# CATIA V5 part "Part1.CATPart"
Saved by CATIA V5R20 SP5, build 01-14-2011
Part number: 饮料瓶
Bounding box of the stored display mesh (mm): x -25 to 26, y -25 to 180.655, z 0 to 110
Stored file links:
  E:\饮料瓶\Part1.CATPart
  C:\Program Files\Dassault Systemes\B20\intel_a\startup\materials\Catalog.CATMaterial
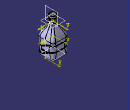
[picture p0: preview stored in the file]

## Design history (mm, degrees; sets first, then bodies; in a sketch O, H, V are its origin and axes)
Set1
  Sketch1 on xy-plane, origin (0, 0, 0), H (1, 0, 0), V (0, 1, 0)
    line L1 (25, 25) -> (25, -25)
    line L2 (25, -25) -> (-25, -25)
    line L3 (-25, -25) -> (-25, 25)
    line L4 (-25, 25) -> (25, 25)
    length L1 = 50
    length L2 = 50
    vertical: L1 V, L3 V
    horizontal: L2 H, L4 H
    equidistance: L1 L3 O, L2 L4 O
  Sketch2 on face of Pad1 from Sketch1.L3, origin (-25, 0, 0), H (0, -1, 0), V (0, 0, 1)
    spline S1 through (-40, 10) (-10, 20) (20, 10) (30, 20) (40, 30)
  Extrude1: Element1 Sketch2, Lim1 80, Lim2 80
  MultiSel1: CommonCtxFeats ({extract ExtractElem face of Pad1 from Sketch1.L3}; {extract ExtractElem face of Fillet1}; {extract ExtractElem face of Pad1 from Sketch1.L2}; {extract ExtractElem face of Fillet1}; {extract ExtractElem face of Pad1 from Sketch1.L1}; {extract ExtractElem face of Fillet1}; {extract ExtractElem face of Pad1 from Sketch1.L4}; {extract ExtractElem face of Fillet1})
  Sketch3 on face of Pad1 from Sketch1.L2, origin (0, -25, 0), H (1, 0, 0), V (0, 0, 1)
    spline S1 through (-30, 30) (-10, 40) (20, 30) (40, 40)
  Extrude2: Element1 Sketch3, Lim1 80, Lim2 80
  Sketch4 on face of Pad1 from Sketch1.L3, origin (-25, 0, 0), H (0, -1, 0), V (0, 0, 1)
    spline S1 through (-40, 30) (-10, 40) (10, 30) (50, 40)
  Extrude3: Element1 Sketch4, Lim1 80, Lim2 80
  MultiSel2: CommonCtxFeats ({extract ExtractElem face of Pad1 from Sketch1.L3}; {extract ExtractElem face of Fillet1}; {extract ExtractElem face of Pad1 from Sketch1.L2}; {extract ExtractElem face of Fillet1}; {extract ExtractElem face of Pad1 from Sketch1.L1}; {extract ExtractElem face of Fillet1}; {extract ExtractElem face of Pad1 from Sketch1.L4}; {extract ExtractElem face of Fillet1})
  Join1: Elements ({intersect ToIntersect1 {extract ExtractElem face of Pad1 from Sketch1.L3}, ToIntersect2 Extrude1}; {intersect ToIntersect1 {extract ExtractElem face of Fillet1}, ToIntersect2 Extrude1}; {intersect ToIntersect1 {extract ExtractElem face of Pad1 from Sketch1.L2}, ToIntersect2 Extrude1}; {intersect ToIntersect1 {extract ExtractElem face of Fillet1}, ToIntersect2 Extrude1}; {intersect ToIntersect1 {extract ExtractElem face of Pad1 from Sketch1.L1}, ToIntersect2 Extrude1}; {intersect ToIntersect1 {extract ExtractElem face of Fillet1}, ToIntersect2 Extrude1}; {intersect ToIntersect1 {extract ExtractElem face of Pad1 from Sketch1.L4}, ToIntersect2 Extrude1}; {intersect ToIntersect1 {extract ExtractElem face of Fillet1}, ToIntersect2 Extrude1})
  Join2: Elements ({intersect ToIntersect1 {extract ExtractElem face of Pad1 from Sketch1.L3}, ToIntersect2 Extrude3}; {intersect ToIntersect1 {extract ExtractElem face of Fillet1}, ToIntersect2 Extrude3}; {intersect ToIntersect1 {extract ExtractElem face of Pad1 from Sketch1.L2}, ToIntersect2 Extrude3}; {intersect ToIntersect1 {extract ExtractElem face of Fillet1}, ToIntersect2 Extrude3}; {intersect ToIntersect1 {extract ExtractElem face of Pad1 from Sketch1.L1}, ToIntersect2 Extrude3}; {intersect ToIntersect1 {extract ExtractElem face of Fillet1}, ToIntersect2 Extrude3}; {intersect ToIntersect1 {extract ExtractElem face of Pad1 from Sketch1.L4}, ToIntersect2 Extrude3}; {intersect ToIntersect1 {extract ExtractElem face of Fillet1}, ToIntersect2 Extrude3})
  Plane1: type Normal, Curve Join1, RefPoint vertex [face of MultiSel1 | face of MultiSel1]
  Circle1: type CtrRad, Start 0, End 180, Center vertex [face of MultiSel1 | face of MultiSel1], Support Plane1, Radius 1, FirstDirection (1, 0, 0)
  Plane2: type Normal, Curve Join2, RefPoint vertex [face of MultiSel2 | face of MultiSel2]
  Circle2: type CtrRad, Start 0, End 180, Center vertex [face of MultiSel2 | face of MultiSel2], Support Plane2, Radius 1, FirstDirection (0, 1, 0)
Body1 (main body)
  Pad1: profile Sketch1, direction (0, 0, 1), length 50
  Fillet1: on edge [face of Pad1 from Sketch1.L2 | face of Pad1 from Sketch1.L3]; edge [face of Pad1 from Sketch1.L3 | face of Pad1 from Sketch1.L4]; edge [face of Pad1 from Sketch1.L4 | face of Pad1 from Sketch1.L1]; edge [face of Pad1 from Sketch1.L1 | face of Pad1 from Sketch1.L2]
  Plane3: type Offset, RefPlane xy-plane, Offset 90
  Sketch5 on Plane3, origin (0, 0, 90), H (1, 0, 0), V (0, 1, 0)
    circle A1 centre (0, 0) radius 10
  Pad2: profile Sketch5, direction (0, 0, 1), length 20
  Fillet2: radius 5, on edge [start face of Pad1 | face of Pad1 from Sketch1.L2]
  Sketch6 on end face of Pad1, origin (0, 0, 50), H (1, 0, 0), V (0, 1, 0)
    point P1 (25, 0)
    distance V P1 = 25
  Sketch7 on Plane3, origin (0, 0, 90), H (1, 0, 0), V (0, 1, 0)
    point P1 (10, 0)
    distance V P1 = 10
    coincidence: P1 H
  Loft1: solid, Sections ({boundary Boundary {extract ExtractElem start face of Pad2}}; {boundary Boundary {extract ExtractElem end face of Pad1}}), StartFace start face of Pad2, EndFace end face of Pad1
  Slot1: profile Circle2, centre curve Join2
  Slot2: profile Circle1, centre curve Join1
  Shell1: ExtOffset 0, Face end face of Pad2, IntOffset 1
  Plane4: type Offset, RefPlane xy-plane, Offset 92
  Sketch8 on Plane4, origin (0, 0, 92), H (1, 0, 0), V (0, 1, 0)
    point P1 (10, 0)
    distance O P1 = 10
    coincidence: P1 H
  Helix1: Direction Z axis, RefPoint Sketch8, Pitch 3, Height 15, TaperAngle 0
  Point1: type OnCurve, Support Helix1, Length 5
  Point2: type OnCurve, Support Helix1, Length 5
  Line1: type PtDir, RefPoint vertex of Helix1, Direction (1, 0, 0), Start 0, End -5
  Line2: type PtDir, RefPoint Sketch8, Direction (1, 0, 0), Start 0, End -5
  Connect1: Curve1 Line2, Point1 vertex of Line2, Tension1 1, Curve2 Helix1, Point2 Point1, Tension2 1
  Connect2: Curve1 Line1, Point1 vertex of Line1, Tension1 1, Curve2 Connect1, Point2 Point2, Tension2 1
  Plane5: type Normal, Curve Connect2, RefPoint vertex of Connect2
  Circle3: type CtrRad, Start 0, End 180, Radius 1, Center vertex of Connect2, Support Plane5, FirstDirection (0, 1, 0)
  Rib1: profile Circle3, centre curve Connect2
  Sketch9 on Plane4, origin (0, 0, 92), H (1, 0, 0), V (0, 1, 0)
    circle A1 centre (0, 0) radius 9
  Pocket1: profile Sketch9, direction (0, 0, 1), length 20
Body2
  Sketch10 on face of Pad1 from Sketch1.L1, origin (25, 0, 0), H (0, 1, 0), V (0, 0, 1)
    polyline C1
    polyline C2
    polyline C3
    polyline C4
    polyline C5
    polyline C6
    polyline C7
    polyline C8
    polyline C9
    polyline C10
    polyline C11
  Sketch11 on face of Pad1 from Sketch1.L1, origin (25, 0, 0), H (0, 1, 0), V (0, 0, 1)
    polyline C1
    polyline C2
    polyline C3
    polyline C4
    polyline C5
    polyline C6
    polyline C7
    polyline C8
    polyline C9
    polyline C10
    polyline C11
  Pad3: profile Sketch11, direction (1, 0, 0), length 1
